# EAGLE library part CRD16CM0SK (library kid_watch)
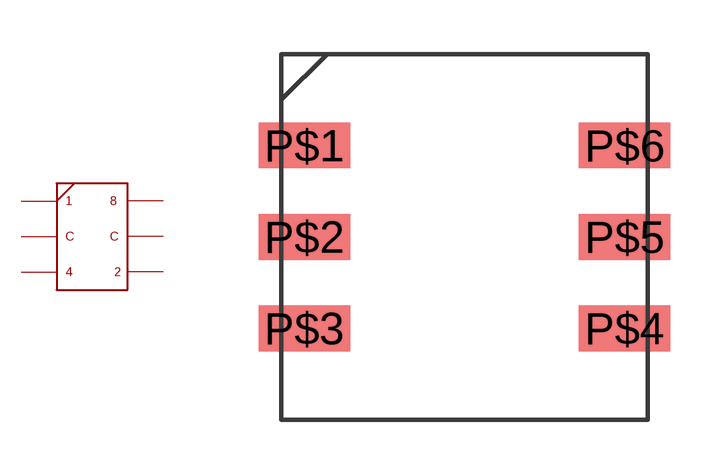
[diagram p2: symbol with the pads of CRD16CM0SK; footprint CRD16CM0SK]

Designator prefix -

## CRD16CM0SK  [CRD16CM0SK]
P$1  P$1
P$2  P$2
P$3  P$3
P$4  P$4
P$5  P$5
P$6  P$6

## Footprint CRD16CM0SK (pad centres in mm)
smd 2.54 x 1.27: P$1 0,2.54; P$2 0,0; P$3 0,-2.54; P$4 8.89,-2.54; P$5 8.89,0; P$6 8.89,2.54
